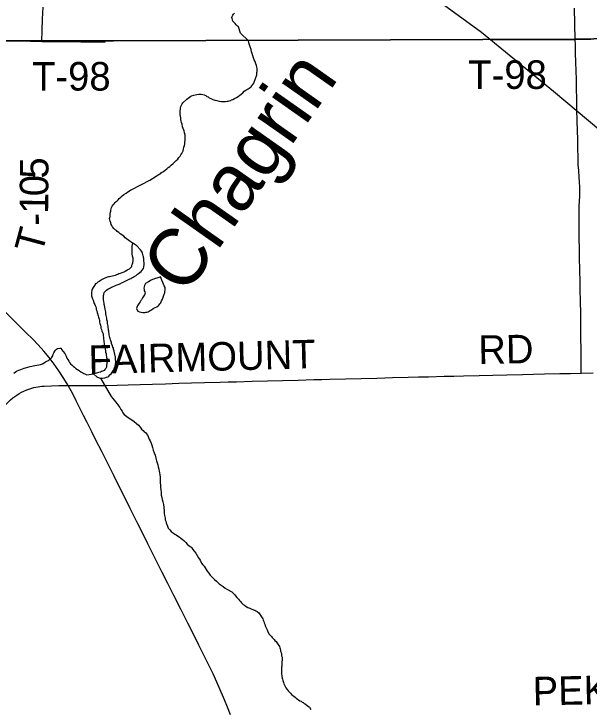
# Model space of a CAD drawing. Extents: x 103424 to 286016, y 38711 to 110967.
# Drawn here: x 119854 to 125931, y 63924 to 71273 of the extents above; entities that cross this region are included whole.
import ezdxf

# ---------------------------------------------------------------- set-up
doc = ezdxf.new("R2010")
doc.units = 0
for name, color, linetype in [('GM_X_Corporation', 7, 'Continuous'), ('GM_X_County_Road', 7, 'Continuous'), ('GM_X_County_Road_Text', 7, 'Continuous'), ('GM_X_Major_River', 7, 'Continuous'), ('GM_X_Major_River_Text', 7, 'Continuous'), ('GM_X_Minor_Lake', 7, 'Continuous'), ('GM_X_Minor_River', 7, 'Continuous'), ('GM_X_Rail_Line', 7, 'Continuous'), ('GM_X_Township_Road', 7, 'Continuous'), ('GM_X_Township_Road_Text', 7, 'Continuous')]:
    doc.layers.add(name, color=color, linetype=linetype)

msp = doc.modelspace()

# ---------------------------------------------------------------- linework, layer by layer
at = {"layer": 'GM_X_Corporation'}
for points in [[(127353.3, 71034.4), (125782.9, 71007.1), (120904.4, 70988.4), (120770.1, 70987.9), (120536.9, 70987), (120142.1, 70987.1), (119688.2, 70990.2), (119635, 74016.7)], [(119747.3, 63220.6), (119711.4, 67089.1), (119699.4, 68185.2), (119697.8, 68222.7), (119697.6, 68351.3), (119691.9, 68458.1), (119686.6, 68980.3), (119689.3, 69057.6), (119689.9, 69111.8), (119690.7, 69193.8), (119690.7, 69692.5), (119693.5, 70192.5), (119690.7, 70601.3), (119688.2, 70990.2), (120142.1, 70987.1), (120536.9, 70987), (120770.1, 70987.9), (120904.4, 70988.4), (125782.9, 71007.1), (127353.3, 71034.4)]]:
    msp.add_lwpolyline(points, dxfattribs=at)
at = {"layer": 'GM_X_County_Road'}
for points in [[(120427.6, 67345.3), (120382.4, 67419.4), (120329.7, 67498.4), (120279.9, 67570.5), (120225.9, 67639.8), (120168.7, 67708.6), (120110.7, 67773.3), (120052.8, 67833.9), (119981, 67904.6), (119909.2, 67975.4), (119802.3, 68080.8), (119695.4, 68186.1)], [(120427.6, 67345.3), (120567.8, 67346), (120696.9, 67345.3), (120826, 67344.7), (120943.6, 67347.3), (121061.1, 67349.9), (121189.5, 67353.8), (121317.9, 67357.7), (121456.8, 67362.7), (121595.7, 67367.6), (121731.6, 67371.2), (121867.6, 67374.8), (122032.6, 67379.3), (122119.4, 67381.7), (122206.3, 67384), (122371.3, 67388.7), (122532.2, 67393.4), (122693.2, 67398.1), (122858.2, 67402.4), (123023.2, 67406.8), (123108, 67409), (123192.8, 67411.2), (123357.8, 67415.4), (123522.8, 67419.5), (123687.8, 67423.6), (123771.4, 67425.7), (123854.9, 67427.8), (124019.9, 67432), (124127.4, 67434.8), (124234.9, 67437.6), (124399.9, 67441.9), (124501.5, 67444.5), (124603, 67447.1), (124768, 67450.5), (124914.6, 67453.6), (125061.2, 67456.6), (125226.2, 67460.6), (125342.4, 67463.4), (125458.6, 67466.2), (125623.6, 67470.3), (125735.7, 67473.1), (125847.8, 67475.9), (125973.6, 67478.2)], [(119711.4, 67084.4), (119767.5, 67142.8), (119797.5, 67172.2), (119818.1, 67192.5), (119843.6, 67214.1), (119864.3, 67228.3), (119885.4, 67243.6), (119910.4, 67260.3), (119933.7, 67273.7), (119960.2, 67286.1), (119992, 67299.5), (120032.8, 67314.3), (120063.3, 67322.5), (120085.4, 67327.6), (120108.5, 67332), (120127.3, 67334.6), (120147.4, 67336.4), (120173.9, 67337.7), (120330, 67343.3), (120427.6, 67345.3)], [(122141.4, 63864.8), (122109.6, 63943.4), (122077.8, 64022), (122022.8, 64151.1), (121958.6, 64295.8), (121920.6, 64373.4), (121882.6, 64451.1), (121808.4, 64598.5), (121749.9, 64714.8), (121691.3, 64831.1), (121617, 64978.5), (121542.7, 65125.9), (121479.9, 65250.4), (121417.2, 65375), (121343.5, 65522.7), (121269.8, 65670.4), (121211.3, 65787.6), (121152.8, 65904.8), (121079.1, 66052.5), (121028.5, 66153.9), (120977.9, 66255.2), (120908.1, 66394.5), (120838.4, 66533.7), (120781.4, 66647.3), (120724.4, 66761), (120676, 66856.4), (120627.6, 66951.9), (120589.1, 67028.7), (120550.7, 67105.5), (120512.8, 67181.4), (120474.8, 67257.2), (120427.6, 67345.3)]]:
    msp.add_lwpolyline(points, dxfattribs=at)
at = {"layer": 'GM_X_Major_River'}
for points in [[(122248.6, 71069.3), (122227.5, 71136), (122217.3, 71142), (122203, 71156), (122190.7, 71170), (122176.4, 71184), (122168.2, 71196.1), (122162, 71210.1), (122159.8, 71224.3), (122157.7, 71234.3), (122159.5, 71246.5), (122165.5, 71258.6), (122175.4, 71268.8), (122185.4, 71279.1)], [(121753.8, 70414.5), (121767.9, 70418.8), (121786, 70421.1), (121806.2, 70423.5), (121832.4, 70423.9), (121850.6, 70420.2), (121862.7, 70418.3), (121881.1, 70408.6), (121891.3, 70400.6), (121905.5, 70394.8), (121917.8, 70386.9), (121936, 70379.1), (121956.4, 70369.4), (121976.7, 70361.6), (121999, 70355.9), (122021.3, 70350.2), (122047.6, 70346.6), (122069.8, 70345), (122090, 70347.3), (122106.1, 70349.6), (122118.1, 70351.8), (122128.2, 70352), (122144.3, 70356.3), (122154.3, 70362.5), (122168.3, 70368.8), (122184.3, 70377.2), (122204.3, 70387.6), (122224.3, 70400), (122240.2, 70412.4), (122256.1, 70424.8), (122272.1, 70439.2), (122287.9, 70455.6), (122303.9, 70466), (122313.8, 70474.2), (122329.9, 70480.6), (122339.9, 70486.8), (122349.8, 70495), (122359.8, 70501.3), (122367.7, 70511.5), (122377.6, 70525.8), (122387.4, 70542.1), (122395.1, 70560.4), (122402.9, 70580.8), (122420.3, 70627.5), (122420.1, 70637.6), (122421.9, 70651.8), (122423.7, 70663.9), (122425.4, 70680.1), (122423.1, 70696.2), (122420.9, 70708.3), (122416.6, 70726.4), (122410.2, 70744.5), (122401.7, 70768.6), (122391.4, 70786.6), (122385, 70806.7), (122378.5, 70830.9), (122372.1, 70853), (122365.7, 70873.1), (122359.2, 70897.2), (122350.7, 70923.3), (122342.3, 70945.4), (122335.8, 70967.6), (122331.5, 70987.7), (122248.6, 71069.3)], [(121106.2, 68848.2), (121030.4, 68905.6), (121014, 68921.5), (120977.3, 68947.2), (120960.9, 68961), (120946.6, 68970.9), (120936.3, 68982.9), (120924.1, 68990.7), (120909.8, 69002.6), (120895.3, 69020.6), (120889, 69034.6), (120882.8, 69046.6), (120876.5, 69062.7), (120870.1, 69082.8), (120865.8, 69094.8), (120863.5, 69111), (120867.4, 69121.1), (120869.3, 69131.3), (120871, 69145.4), (120870.8, 69157.6), (120874.6, 69175.8), (120876.4, 69185.9), (120878.2, 69198.1), (120882, 69212.3), (120885.8, 69226.5), (120893.7, 69238.7), (120903.5, 69253.1), (120913.4, 69265.3), (120923.3, 69277.6), (120933.2, 69287.9), (120943.1, 69298.1), (120955.1, 69308.4), (120967, 69320.8), (120982.9, 69335.2), (120996.8, 69349.5), (121014.7, 69362), (121038.7, 69376.5), (121056.6, 69390.9), (121086.6, 69409.6), (121122.6, 69428.4), (121160.6, 69447.2), (121194.6, 69465.9), (121230.6, 69484.7), (121262.6, 69501.4), (121290.6, 69516), (121356.5, 69557.5), (121378.5, 69569.9), (121394.5, 69580.3), (121404.5, 69586.5), (121414.4, 69594.8), (121428.4, 69603.1), (121438.4, 69609.3), (121450.3, 69621.6), (121468.2, 69636.1), (121484.1, 69648.5), (121500.1, 69660.8), (121514, 69673.2), (121535.9, 69689.7), (121549.8, 69706.1), (121569.7, 69722.6), (121585.6, 69737), (121597.4, 69753.4), (121609.3, 69767.7), (121619.1, 69782), (121626.9, 69798.3), (121634.8, 69812.6), (121640.6, 69826.8), (121646.4, 69843), (121650, 69865.3), (121655.8, 69881.6), (121659.5, 69899.8), (121661.3, 69916), (121663, 69934.2), (121664.7, 69952.4), (121662.4, 69968.6), (121662.1, 69990.8), (121657.6, 70015), (121651.2, 70037.1), (121642.7, 70061.2), (121636.4, 70079.3), (121629.9, 70105.4), (121623.5, 70123.5), (121621.2, 70139.6), (121618.9, 70155.7), (121616.6, 70173.9), (121614.3, 70192), (121612, 70210.2), (121611.7, 70228.4), (121611.3, 70248.6), (121613.1, 70264.8), (121614.9, 70276.9), (121616.6, 70293.1), (121624.5, 70307.4), (121632.3, 70323.6), (121640.2, 70333.9), (121679.9, 70372.9), (121693.8, 70383.2), (121707.8, 70393.6), (121721.8, 70401.9), (121731.8, 70406.1), (121753.8, 70414.5)], [(120875, 67828.3), (120870.7, 67840.3), (120866.5, 67852.4), (120864.2, 67866.5), (120862, 67880.6), (120859.8, 67890.6), (120857.5, 67904.7), (120855.3, 67918.8), (120853.1, 67930.9), (120852.8, 67945.1), (120850.6, 67957.2), (120848.3, 67973.3), (120846.1, 67985.4), (120843.8, 68001.5), (120841.5, 68019.6), (120837.1, 68037.7), (120834.8, 68055.9), (120832.5, 68072), (120830.3, 68086.1), (120826, 68102.2), (120823.7, 68118.3), (120821.3, 68136.5), (120819.1, 68150.6), (120810.4, 68190.9), (120808.2, 68200.9), (120806, 68211), (120803.6, 68231.1), (120801.3, 68249.3), (120801.1, 68263.4), (120800.8, 68279.6), (120800.5, 68295.7), (120802.3, 68307.9), (120808.1, 68326.2), (120821.9, 68342.6), (120833.9, 68352.9), (120847.8, 68363.2), (120861.8, 68371.5), (120873.8, 68375.7), (120883.8, 68384), (120893.8, 68388.2), (120903.8, 68392.4), (120919.9, 68398.7), (120933.9, 68405), (120943.9, 68409.2), (120954, 68411.4), (120982, 68424), (120992, 68430.2), (121002, 68434.4), (121014, 68440.7), (121028, 68449), (121078.1, 68472), (121088.1, 68476.2), (121100.1, 68482.5), (121114.1, 68490.8), (121126.1, 68497.1), (121144.1, 68507.5), (121158, 68519.8), (121171.9, 68530.1), (121185.9, 68538.5), (121197.8, 68550.8), (121207.7, 68563.1), (121221.5, 68581.5), (121225.3, 68595.7), (121227.1, 68607.8), (121229, 68617.9), (121230.8, 68630.1), (121228.5, 68644.2), (121228.3, 68660.4), (121228.1, 68670.5), (121225.8, 68686.6), (121221.6, 68696.6), (121221.4, 68706.7), (121219.3, 68716.8), (121217, 68728.9), (121212.8, 68742.9), (121208.6, 68753), (121202.3, 68765), (121192, 68776.9), (121152.9, 68820.8), (121130.5, 68836.5), (121116.2, 68844.4), (121106.2, 68848.2)], [(121106.2, 68848.2), (121102.3, 68834.1), (121100.6, 68815.9), (121100.8, 68803.7), (121101, 68789.6), (121101.2, 68777.5), (121099.4, 68763.3), (121099.6, 68751.2), (121099.9, 68733), (121104.3, 68714.9), (121108.7, 68692.7), (121111, 68676.6), (121111.2, 68662.5), (121107.4, 68646.3), (121105.6, 68636.1), (121101.7, 68626), (121097.9, 68613.8), (121096.1, 68597.6), (121086.2, 68587.3), (121072.3, 68573)], [(121072.3, 68573), (121058.3, 68566.7), (121046.4, 68558.4), (121030.3, 68550), (121016.3, 68543.8), (121006.3, 68539.5), (120994.3, 68535.3), (120978.2, 68529), (120964.2, 68524.7), (120950.2, 68518.4), (120938.1, 68514.2), (120924.1, 68507.9), (120910, 68503.6), (120896, 68501.4), (120877.9, 68497), (120863.8, 68494.8), (120851.7, 68492.6), (120837.7, 68488.3), (120825.7, 68482), (120813.6, 68477.8), (120799.6, 68471.5), (120787.6, 68465.2), (120765.6, 68450.7), (120753.6, 68444.5), (120741.7, 68436.2), (120725.7, 68423.8), (120715.8, 68417.6), (120705.9, 68403.3), (120698, 68391), (120690.2, 68378.8), (120680.3, 68364.5), (120678.5, 68354.3), (120676.6, 68344.2), (120674.8, 68330), (120675, 68317.9), (120673.2, 68305.8), (120675.4, 68293.7), (120684.1, 68261.5), (120692.4, 68245.5), (120698.8, 68223.4), (120703.1, 68211.3), (120709.3, 68201.3), (120713.5, 68191.3), (120717.8, 68177.2), (120722, 68163.1), (120724.3, 68149), (120728.6, 68132.9), (120732.9, 68116.8), (120737.1, 68106.8), (120739.3, 68092.7), (120745.6, 68080.7), (120747.9, 68066.6), (120750, 68056.5), (120754.3, 68044.5), (120756.5, 68030.4), (120758.8, 68014.2), (120763.1, 68000.2), (120767.4, 67982.1), (120771.8, 67966), (120774, 67951.9), (120778.3, 67937.8), (120784.6, 67921.7), (120790.9, 67903.6), (120795.2, 67889.6), (120797.6, 67871.4), (120799.9, 67853.3), (120800.2, 67835.1), (120802.4, 67821), (120804.6, 67808.9), (120807, 67788.8), (120809.2, 67776.7), (120813.5, 67764.6), (120815.7, 67750.5), (120818.1, 67730.3), (120820.4, 67712.2), (120822.7, 67696.1), (120827, 67680), (120829.3, 67663.9), (120831.5, 67651.8), (120833.7, 67639.7), (120838, 67623.6), (120840.3, 67609.5), (120838.5, 67595.3), (120836.6, 67585.2), (120833.2, 67552.8), (120831.4, 67538.6), (120825.6, 67524.4), (120815.6, 67514.1), (120809.8, 67503.9), (120799.7, 67499.7), (120789.7, 67497.5), (120779.7, 67493.3), (120767.7, 67487.1), (120749.6, 67482.7), (120737.5, 67478.5), (120725.5, 67474.3), (120703.4, 67469.9), (120695.8, 67468.6)], [(120695.8, 67468.6), (120734.3, 67432), (120736.3, 67432), (120766.8, 67420.4), (120776.9, 67420.6), (120790.9, 67422.8), (120813.1, 67427.2), (120833.1, 67433.6), (120847.2, 67435.9), (120857.2, 67444.1), (120869.1, 67456.4), (120881, 67466.7), (120896.8, 67489.2), (120904.6, 67505.5), (120912.4, 67519.8), (120918.2, 67534), (120922, 67548.2), (120927.8, 67566.5), (120929.3, 67592.8), (120929.2, 67602.9), (120926.9, 67619), (120926.6, 67639.2), (120926.4, 67649.3), (120924.2, 67659.4), (120921.9, 67673.5), (120917.6, 67689.6), (120913.3, 67707.7), (120911.1, 67719.7), (120906.9, 67729.8), (120904.7, 67739.8), (120900.5, 67749.9), (120894.1, 67768), (120889.9, 67778), (120885.7, 67788), (120883.5, 67798.1), (120877.2, 67816.2), (120875, 67828.3)], [(119853.7, 67476.1), (119881.7, 67494.8), (119905.7, 67505.3), (119927.7, 67513.7), (119945.8, 67522.1), (119961.8, 67526.4), (119977.9, 67532.7), (120026.1, 67545.6), (120042.2, 67547.9), (120058.3, 67552.2), (120074.4, 67554.5), (120094.5, 67558.9), (120116.6, 67563.3), (120134.7, 67567.6), (120154.8, 67574), (120174.8, 67584.4), (120192.7, 67598.9), (120218.8, 67609.4), (120230.7, 67617.7), (120240.6, 67627.9), (120250.6, 67636.2), (120258.5, 67646.4), (120266.3, 67658.7), (120270.1, 67676.9), (120275.9, 67691.1), (120285.7, 67707.5), (120291.6, 67717.7), (120305.6, 67728), (120315.5, 67734.2), (120337.6, 67740.6), (120351.7, 67740.9), (120356.1, 67724.8), (120391.1, 67682.9), (120397.3, 67668.9), (120407.7, 67654.9), (120414.1, 67634.8), (120424.4, 67618.8), (120432.8, 67602.8), (120441.1, 67588.8), (120453.4, 67572.8), (120467.8, 67558.9), (120480.1, 67549), (120492.4, 67537.1), (120508.7, 67525.3), (120525.1, 67513.4), (120543.4, 67501.6), (120559.8, 67489.7), (120582.2, 67478), (120594.4, 67470.1), (120608.6, 67464.3), (120624.9, 67458.5), (120695.8, 67468.6)]]:
    msp.add_lwpolyline(points, dxfattribs=at)
at = {"layer": 'GM_X_Minor_Lake'}
for points in [[(121149.9, 68160.1), (121156.3, 68140), (121164.5, 68130), (121180.8, 68124.2), (121199, 68120.5), (121217.2, 68116.7), (121237.4, 68117), (121249.5, 68119.3), (121259.5, 68121.4), (121271.6, 68123.7), (121281.6, 68129.9), (121293.5, 68138.2), (121307.6, 68144.5), (121325.5, 68156.9), (121347.5, 68169.4), (121365.5, 68177.7), (121377.5, 68186), (121387.4, 68196.3), (121397.3, 68206.5), (121407.2, 68218.8), (121414.9, 68239.2), (121424.7, 68255.5), (121442, 68310.3), (121447.8, 68322.5), (121449.6, 68336.7), (121451.4, 68350.9), (121453.2, 68363), (121450.9, 68381.2), (121440.5, 68399.2), (121402.6, 68491.5)], [(121402.6, 68491.5), (121386.6, 68485.2), (121362.5, 68478.7), (121346.4, 68474.4), (121332.4, 68470.1), (121318.3, 68463.8), (121304.3, 68457.6), (121292.4, 68449.3), (121276.3, 68440.9), (121244.4, 68422.2), (121234.7, 68399.9), (121228.8, 68387.6), (121227, 68373.5), (121229.3, 68359.4), (121231.5, 68345.2), (121235.7, 68335.2), (121240, 68321.1), (121232.3, 68302.8), (121226.4, 68292.6), (121220.5, 68282.4), (121212.6, 68270.2), (121202.8, 68251.8), (121194.9, 68241.6), (121187.1, 68229.4), (121177.2, 68215.1), (121169.3, 68204.8), (121161.5, 68192.6), (121155.6, 68180.4), (121151.7, 68170.2), (121149.9, 68160.1)], [(121402.6, 68491.5), (121386.6, 68485.2), (121362.5, 68478.7), (121346.4, 68474.4), (121332.4, 68470.1), (121318.3, 68463.8), (121304.3, 68457.6), (121292.4, 68449.3), (121276.3, 68440.9), (121244.4, 68422.2), (121234.7, 68399.9), (121228.8, 68387.6), (121227, 68373.5), (121229.3, 68359.4), (121231.5, 68345.2), (121235.7, 68335.2), (121240, 68321.1), (121232.3, 68302.8), (121226.4, 68292.6), (121220.5, 68282.4), (121212.6, 68270.2), (121202.8, 68251.8), (121194.9, 68241.6), (121187.1, 68229.4), (121177.2, 68215.1), (121169.3, 68204.8), (121161.5, 68192.6), (121155.6, 68180.4), (121151.7, 68170.2), (121149.9, 68160.1), (121156.3, 68140), (121164.5, 68130), (121180.8, 68124.2), (121199, 68120.5), (121217.2, 68116.7), (121237.4, 68117), (121249.5, 68119.3), (121259.5, 68121.4), (121271.6, 68123.7), (121281.6, 68129.9), (121293.5, 68138.2), (121307.6, 68144.5), (121325.5, 68156.9), (121347.5, 68169.4), (121365.5, 68177.7), (121377.5, 68186), (121387.4, 68196.3), (121397.3, 68206.5), (121407.2, 68218.8), (121414.9, 68239.2), (121424.7, 68255.5), (121442, 68310.3), (121447.8, 68322.5), (121449.6, 68336.7), (121451.4, 68350.9), (121453.2, 68363), (121450.9, 68381.2), (121440.5, 68399.2), (121402.6, 68491.5)]]:
    msp.add_lwpolyline(points, dxfattribs=at)
at = {"layer": 'GM_X_Minor_River'}
for points in [[(120768.4, 67420.4), (120883, 67228.3), (120899.5, 67208.4), (120913.9, 67188.5), (120930.4, 67168.5), (120971.7, 67110.6), (120984.1, 67092.6), (120996.6, 67072.6), (121005, 67054.6), (121017.3, 67038.6), (121046, 67016.9), (121070.5, 66999.1), (121099, 66981.4), (121125.5, 66963.6), (121148.1, 66943.8), (121170.6, 66924), (121189.1, 66904.1), (121203.6, 66882.1), (121218, 66868.2), (121230.3, 66856.3), (121242.5, 66848.4), (121252.8, 66838.4), (121267.3, 66814.4), (121275.7, 66794.4), (121284.1, 66776.3), (121294.5, 66758.3), (121302.9, 66736.2), (121311.4, 66712.1), (121319.9, 66688), (121326.3, 66661.9), (121334.9, 66633.7), (121345.4, 66607.6), (121354, 66575.4), (121360.5, 66549.3), (121369, 66527.2), (121373.3, 66507.1), (121377.7, 66484.9), (121384.2, 66460.8), (121388.6, 66440.6), (121393, 66420.5), (121395.3, 66400.4), (121397.8, 66374.1), (121400.2, 66347.9), (121400.8, 66315.6), (121401.2, 66291.3), (121403.6, 66265.1), (121406.1, 66240.9), (121408.5, 66214.7), (121411, 66186.4), (121415.4, 66162.3), (121419.9, 66138.1), (121426.3, 66116), (121430.6, 66099.9), (121432.8, 66087.8), (121440, 66019.3), (121442.5, 65993), (121444.9, 65970.8), (121447.2, 65954.7), (121451.4, 65940.6), (121453.7, 65924.5), (121458, 65910.4), (121464.3, 65894.4), (121470.7, 65876.3), (121477, 65858.2), (121485.4, 65838.2), (121499.9, 65820.2), (121514.3, 65802.3), (121528.6, 65790.4), (121540.9, 65782.5), (121553.1, 65774.6), (121569.4, 65764.8), (121583.7, 65756.9), (121600, 65745.1), (121616.4, 65731.2), (121632.7, 65719.4), (121649.1, 65705.5), (121669.7, 65683.6), (121686.1, 65665.7), (121706.5, 65649.9), (121722.9, 65638), (121735.2, 65628.1), (121745.5, 65612.1), (121760, 65592.1), (121774.4, 65572.2), (121791, 65548.2), (121805.6, 65522.2), (121820.1, 65498.2), (121834.7, 65466.1), (121851.2, 65450.2), (121863.5, 65434.2), (121873.9, 65418.2), (121884.3, 65400.2), (121896.7, 65382.3), (121913.2, 65362.3), (121927.7, 65340.3), (121944.1, 65320.4), (121960.5, 65306.5), (121974.9, 65292.6)], [(121974.9, 65292.6), (121993.3, 65274.7), (122024, 65249), (122044.5, 65233.2), (122064.9, 65219.4), (122087.4, 65203.6), (122109.8, 65189.8), (122156.7, 65162.3), (122171, 65150.4), (122183.3, 65136.4), (122195.7, 65122.5), (122210.1, 65102.5), (122226.5, 65086.6), (122238.9, 65072.7), (122249.2, 65060.7), (122259.5, 65048.8), (122277.9, 65030.9), (122290.2, 65021), (122308.5, 65009.2), (122326.9, 64999.4), (122347.2, 64989.6), (122361.4, 64983.8), (122383.8, 64974.1), (122398, 64970.2), (122410.2, 64964.4), (122422.4, 64956.5), (122440.9, 64940.6), (122449.1, 64930.7), (122457.4, 64920.7), (122469.8, 64900.7), (122478.1, 64888.7), (122482.3, 64876.7), (122488.6, 64864.7), (122494.8, 64850.6), (122499.1, 64836.5), (122503.4, 64820.5), (122509.8, 64804.4), (122516.1, 64788.3), (122522.4, 64774.3), (122528.6, 64762.3), (122532.8, 64750.2), (122537.1, 64740.2), (122551.6, 64716.2), (122563.9, 64702.2), (122574.2, 64692.3), (122582.5, 64680.3), (122592.7, 64670.4), (122603, 64660.5), (122611.2, 64650.5), (122623.5, 64638.6), (122635.9, 64622.6), (122658.7, 64584.6), (122663, 64572.6), (122667.2, 64560.5), (122669.4, 64548.4), (122671.6, 64536.3), (122675.9, 64522.3), (122680.3, 64504.1), (122682.5, 64488), (122686.8, 64473.9), (122689.1, 64455.8), (122687.4, 64437.6), (122685.6, 64427.5), (122685.8, 64411.3), (122684.1, 64393.1), (122684.4, 64379), (122682.5, 64368.8), (122682.8, 64354.7), (122681, 64336.5), (122681.3, 64320.3), (122681.6, 64306.2), (122681.8, 64294.1), (122684, 64280), (122686.2, 64267.9), (122688.6, 64249.7), (122690.7, 64239.7), (122695, 64227.6), (122697.2, 64215.5), (122701.4, 64205.5), (122705.7, 64191.4), (122712, 64177.4), (122718.3, 64163.3), (122726.6, 64149.3), (122741, 64131.4), (122751.3, 64117.4), (122763.6, 64105.5), (122776, 64091.5), (122788.3, 64079.6), (122802.6, 64067.7), (122812.8, 64059.8), (122825.1, 64049.9), (122837.4, 64040), (122849.6, 64030.1), (122861.9, 64022.3), (122876.2, 64012.4), (122888.4, 64006.5), (122898.6, 63998.6), (122908.8, 63992.7), (122921, 63984.8), (122931.2, 63978.9), (122955.8, 63959.1)], [(122955.8, 63959.1), (122974.1, 63947.3), (122976.2, 63945.3), (122990.7, 63919.3)]]:
    msp.add_lwpolyline(points, dxfattribs=at)
at = {"layer": 'GM_X_Rail_Line'}
msp.add_lwpolyline([(121943.9, 72984.2), (122182.1, 72897.3), (122415.6, 72812.4), (124792.9, 71078.1), (125556.8, 70456.6), (126295.9, 69834.8), (126924.8, 69218), (127230.6, 68946.2), (127450.9, 68796.9), (129668, 67771.2), (130803.4, 67235.1), (131559.6, 66894.9), (131970.7, 66637.8), (132157, 66481.8), (132734.1, 65975.1), (133539.6, 65148.6), (133726.4, 65044.7), (134046.1, 64920.1), (134199.7, 64783.1), (134531.9, 64172.6), (134681.3, 64064.6), (135221.1, 64052.1), (135711, 63354.4)], dxfattribs=at)
at = {"layer": 'GM_X_Township_Road'}
for points in [[(120147.3, 70982.4), (120151.5, 71099.8), (120155.8, 71217.2), (120163.9, 71343)], [(125784.2, 71003.5), (125781.5, 71168.6), (125778.7, 71333.6)], [(119704.4, 70969.6), (119715.5, 70978.2), (119730.2, 70983.7), (119749.4, 70987.3), (119770.6, 70988.8), (119909.4, 70986.5), (120028.3, 70984.5), (120147.3, 70982.4), (120231.9, 70981.8), (120316.4, 70981.1), (120438.7, 70979.6), (120561, 70978), (120689.4, 70975.9), (120817.7, 70973.7)], [(124897.2, 70999.9), (125033.7, 71000.5), (125170.2, 71001), (125335.2, 71001.7), (125468.5, 71002.3), (125601.9, 71002.8), (125650.1, 71003)], [(125650.1, 71003), (125693, 71003.1), (125784.2, 71003.5), (125949.3, 71006.7)], [(125847.8, 67475.9), (125847.1, 67605), (125845.5, 67968.8), (125843.5, 68089), (125839.9, 68254.1), (125838.2, 68337.7), (125836.3, 68421.3), (125832.8, 68586.4), (125830.8, 68676.8), (125828.9, 68767.2), (125827.3, 68919.5), (125825.7, 69071.8), (125826.1, 69156.6), (125826.5, 69241.3), (125828.7, 69294.7), (125832.9, 69346.9), (125834.6, 69395.6), (125833.8, 69444.4), (125830.8, 69494.5), (125826.6, 69546.1), (125821.1, 69616.5), (125817.2, 69677.5), (125814.7, 69748.4), (125812.6, 69861.1), (125810.9, 69948.2), (125809.2, 70035.3), (125806.2, 70146.1), (125803.3, 70256.8), (125801.1, 70370.2), (125798.8, 70483.6), (125796.5, 70577.4), (125794.3, 70671.3), (125791.6, 70763.6), (125789, 70855.9), (125786.1, 70945.9), (125784.2, 71003.5)], [(120427.6, 67345.3), (120382.4, 67419.4), (120329.7, 67498.4), (120279.9, 67570.5), (120225.9, 67639.8), (120168.7, 67708.6), (120110.7, 67773.3), (120052.8, 67833.9), (119981, 67904.6), (119909.2, 67975.4), (119802.3, 68080.8), (119695.4, 68186.1)], [(122141.4, 63864.8), (122109.6, 63943.4), (122077.8, 64022), (122022.8, 64151.1), (121958.6, 64295.8), (121920.6, 64373.4), (121882.6, 64451.1), (121808.4, 64598.5), (121749.9, 64714.8), (121691.3, 64831.1), (121617, 64978.5), (121542.7, 65125.9), (121479.9, 65250.4), (121417.2, 65375), (121343.5, 65522.7), (121269.8, 65670.4), (121211.3, 65787.6), (121152.8, 65904.8), (121079.1, 66052.5), (121028.5, 66153.9), (120977.9, 66255.2), (120908.1, 66394.5), (120838.4, 66533.7), (120781.4, 66647.3), (120724.4, 66761), (120676, 66856.4), (120627.6, 66951.9), (120589.1, 67028.7), (120550.7, 67105.5), (120512.8, 67181.4), (120474.8, 67257.2), (120427.6, 67345.3)]]:
    msp.add_lwpolyline(points, dxfattribs=at)

# ---------------------------------------------------------------- texts
at = {"layer": 'GM_X_County_Road_Text'}
for s, rotation, p in [('FAIRMOUNT', 1.48947, (120645.5, 67465.4)), ('RD', 0.98724, (124763.2, 67571.6))]:
    msp.add_text(s, height=301.87, rotation=rotation, dxfattribs=at).set_placement(p)
at = {"layer": 'GM_X_Major_River_Text'}
msp.add_text('Chagrin', height=604.14, rotation=54.89589, dxfattribs=at).set_placement((121664.7, 68280.9))
at = {"layer": 'GM_X_Township_Road_Text'}
for s, height, rotation, p in [('T-98', 301.87, 0.00001, (120045.6, 70462)), ('T-98', 301.87, 0.00001, (124654.6, 70479.7)), ('5', 301.9, 89.66747, (120218.2, 69530.8)), ('0', 301.9, 89.63452, (120217, 69344.6)), ('1', 301.9, 89.50042, (120215.3, 69157.9)), ('-', 301.9, 91.79927, (120219.2, 69037.2)), ('T', 301.9, 75.02303, (120149.8, 68723.7)), ('PEKIN', 301.87, 1.15236, (125338, 63962.1))]:
    msp.add_text(s, height=height, rotation=rotation, dxfattribs=at).set_placement(p)

doc.saveas('drawing.dxf')
